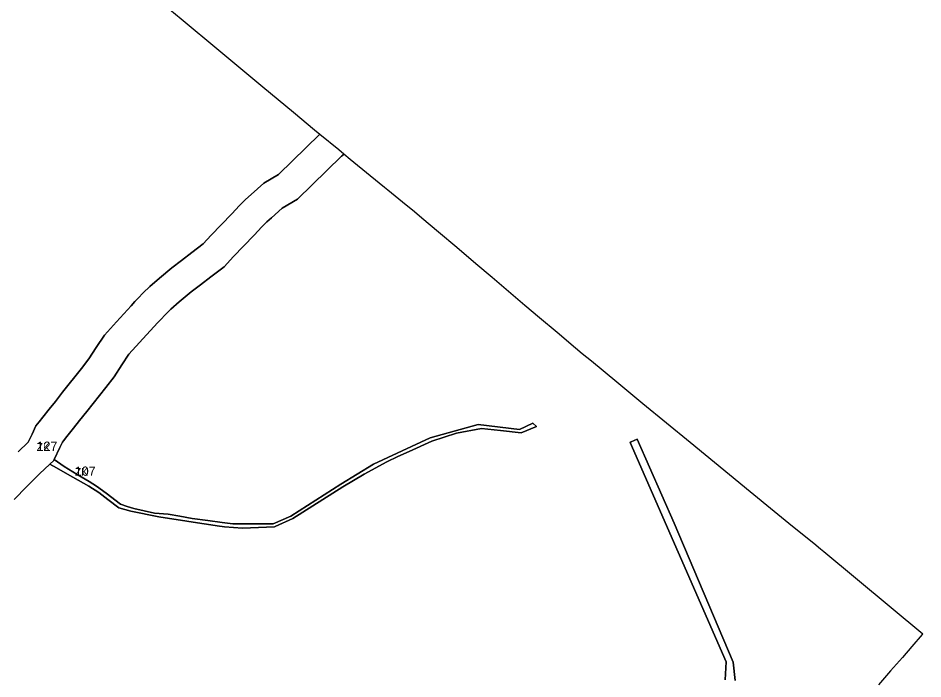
# Model space of a CAD drawing. Extents: x -537068 to -534056, y -1176840 to -1172401.
# Drawn here: x -534942 to -534355, y -1174646 to -1174218 of the extents above; entities that cross this region are included whole.
import ezdxf

# ---------------------------------------------------------------- set-up
doc = ezdxf.new("R2010")
doc.units = 0
for name, color, linetype in [('90640013', 7, 'Continuous'), ('90710023', 7, 'Continuous'), ('90750013', 7, 'Continuous'), ('ID_navrh', 7, 'Continuous')]:
    doc.layers.add(name, color=color, linetype=linetype)

msp = doc.modelspace()

# ---------------------------------------------------------------- linework, layer by layer
at = {"layer": '90640013'}
msp.add_lwpolyline([(-534483.43, -1174646.62), (-534482.82, -1174635.13), (-534544.96, -1174492.85), (-534544.28, -1174492.54), (-534540.56, -1174490.81), (-534516.48, -1174545.24), (-534478.25, -1174635.29), (-534477.06, -1174647.13)], dxfattribs=at)
at = {"layer": '90710023'}
msp.add_lwpolyline([(-534941.55, -1174498.93), (-534934.92, -1174492.67), (-534932.5, -1174487.55), (-534929.97, -1174482.19), (-534927.84, -1174479.51), (-534925.57, -1174476.65), (-534921.36, -1174471.33), (-534917.36, -1174466.29), (-534912.72, -1174460.43), (-534900.49, -1174444.99), (-534895.64, -1174438.72), (-534890.91, -1174431.52), (-534885.55, -1174423.46), (-534877.76, -1174414.85), (-534873.08, -1174409.69), (-534868.28, -1174404.39), (-534865.86, -1174401.72), (-534863.7, -1174399.5), (-534860.41, -1174396.1), (-534856.3, -1174391.86), (-534850, -1174386.58), (-534841.97, -1174379.85), (-534835.63, -1174374.98), (-534828.91, -1174369.82), (-534821.55, -1174364.16), (-534816.37, -1174358.72), (-534809.91, -1174351.94), (-534803.15, -1174344.84), (-534798.02, -1174339.45), (-534794.25, -1174335.5), (-534790.64, -1174332.32), (-534782.33, -1174324.99), (-534772.78, -1174319.35), (-534746, -1174293.24), (-534733.78, -1174303.25), (-534730.46, -1174305.96), (-534731.42, -1174306.96), (-534732.04, -1174307.56), (-534760.54, -1174335.35), (-534770.52, -1174341.25), (-534777.41, -1174347.32), (-534780.38, -1174349.94), (-534783.54, -1174353.25), (-534788.66, -1174358.63), (-534795.43, -1174365.73), (-534801.89, -1174372.51), (-534808.13, -1174379.07), (-534816.72, -1174385.68), (-534823.45, -1174390.84), (-534829.45, -1174395.45), (-534837.15, -1174401.91), (-534842.66, -1174406.52), (-534846.04, -1174410.01), (-534849.35, -1174413.43), (-534851.28, -1174415.41), (-534853.46, -1174417.82), (-534858.26, -1174423.12), (-534862.94, -1174428.28), (-534869.72, -1174435.77), (-534874.23, -1174442.55), (-534879.35, -1174450.35), (-534884.74, -1174457.32), (-534897.04, -1174472.85), (-534901.69, -1174478.71), (-534905.69, -1174483.75), (-534909.9, -1174489.07), (-534912.18, -1174491.95), (-534912.87, -1174492.82), (-534914.42, -1174496.09), (-534918.11, -1174503.91), (-534918.45, -1174504.62), (-534920.96, -1174506.99), (-534927.58, -1174513.24), (-534935.81, -1174521.55), (-534944.09, -1174529.91)], dxfattribs=at)
msp.add_lwpolyline([(-534920.96, -1174506.99), (-534918.45, -1174504.62), (-534918.11, -1174503.91), (-534911.75, -1174508.48), (-534903.27, -1174513.61), (-534895.53, -1174518.3), (-534890.67, -1174521.25), (-534884.57, -1174525.85), (-534875.3, -1174532.85), (-534870.88, -1174534.39), (-534866.59, -1174535.76), (-534859.86, -1174537.23), (-534853.19, -1174538.69), (-534844.4, -1174539.4), (-534836.83, -1174540.72), (-534828.78, -1174542.12), (-534818.52, -1174543.48), (-534809.35, -1174544.69), (-534802.36, -1174545.61), (-534776.33, -1174545.67), (-534764.95, -1174540.64), (-534732.52, -1174520.03), (-534711.23, -1174506.95), (-534686.74, -1174495.63), (-534674.53, -1174489.99), (-534643.44, -1174481.22), (-534616.63, -1174484.53), (-534608.11, -1174480.54), (-534605.76, -1174482.69), (-534615.7, -1174486.77), (-534629.08, -1174485.21), (-534641.32, -1174483.78), (-534657.61, -1174486.93), (-534673.45, -1174491.99), (-534688.29, -1174498.79), (-534695.46, -1174502.07), (-534702.74, -1174505.41), (-534717.31, -1174513.4), (-534731.12, -1174521.65), (-534744.09, -1174529.89), (-534763.58, -1174542.26), (-534774.98, -1174547.3), (-534775.48, -1174547.52), (-534796.2, -1174548.49), (-534807.85, -1174547.56), (-534812.51, -1174546.88), (-534816.77, -1174546.26), (-534825.24, -1174545.03), (-534832.16, -1174544.02), (-534850.47, -1174541.19), (-534868.48, -1174537.39), (-534876.27, -1174535.32), (-534883.41, -1174529.86), (-534889.21, -1174525.43), (-534895.69, -1174521.31), (-534902.53, -1174517.43), (-534909.64, -1174513.4), (-534916.77, -1174509.36)], close=True, dxfattribs=at)
at = {"layer": '90750013'}
for points in [[(-534850.54, -1174206.42), (-534835.97, -1174218.53), (-534811.5, -1174238.86), (-534801.22, -1174247.4), (-534782.96, -1174262.58), (-534763.17, -1174279.02), (-534749.56, -1174290.33), (-534746, -1174293.24), (-534772.78, -1174319.35), (-534782.33, -1174324.99), (-534790.64, -1174332.32), (-534794.25, -1174335.5), (-534798.02, -1174339.45), (-534803.15, -1174344.84), (-534809.91, -1174351.94), (-534816.37, -1174358.72), (-534821.55, -1174364.16), (-534828.91, -1174369.82), (-534835.63, -1174374.98), (-534841.97, -1174379.85), (-534850, -1174386.58), (-534856.3, -1174391.86), (-534860.41, -1174396.1), (-534863.7, -1174399.5), (-534865.86, -1174401.72), (-534868.28, -1174404.39), (-534873.08, -1174409.69), (-534877.76, -1174414.85), (-534885.55, -1174423.46), (-534890.91, -1174431.52), (-534895.64, -1174438.72), (-534900.49, -1174444.99), (-534912.72, -1174460.43), (-534917.36, -1174466.29), (-534921.36, -1174471.33), (-534925.57, -1174476.65), (-534927.84, -1174479.51), (-534929.97, -1174482.19), (-534932.5, -1174487.55), (-534934.92, -1174492.67), (-534941.55, -1174498.93)], [(-534944.09, -1174529.91), (-534935.81, -1174521.55), (-534927.58, -1174513.24), (-534920.96, -1174506.99), (-534916.77, -1174509.36), (-534909.64, -1174513.4), (-534902.53, -1174517.43), (-534895.69, -1174521.31), (-534889.21, -1174525.43), (-534883.41, -1174529.86), (-534876.27, -1174535.32), (-534868.48, -1174537.39), (-534850.47, -1174541.19), (-534832.16, -1174544.02), (-534825.24, -1174545.03), (-534816.77, -1174546.26), (-534812.51, -1174546.88), (-534807.85, -1174547.56), (-534796.2, -1174548.49), (-534775.48, -1174547.52), (-534774.98, -1174547.3), (-534763.58, -1174542.26), (-534744.09, -1174529.89), (-534731.12, -1174521.65), (-534717.31, -1174513.4), (-534702.74, -1174505.41), (-534695.46, -1174502.07), (-534688.29, -1174498.79), (-534673.45, -1174491.99), (-534657.61, -1174486.93), (-534641.32, -1174483.78), (-534629.08, -1174485.21), (-534615.7, -1174486.77), (-534605.76, -1174482.69), (-534608.11, -1174480.54), (-534616.63, -1174484.53), (-534643.44, -1174481.22), (-534674.53, -1174489.99), (-534686.74, -1174495.63), (-534711.23, -1174506.95), (-534732.52, -1174520.03), (-534764.95, -1174540.64), (-534776.33, -1174545.67), (-534802.36, -1174545.61), (-534809.35, -1174544.69), (-534818.52, -1174543.48), (-534828.78, -1174542.12), (-534836.83, -1174540.72), (-534844.4, -1174539.4), (-534853.19, -1174538.69), (-534859.86, -1174537.23), (-534866.59, -1174535.76), (-534870.88, -1174534.39), (-534875.3, -1174532.85), (-534884.57, -1174525.85), (-534890.67, -1174521.25), (-534895.53, -1174518.3), (-534903.27, -1174513.61), (-534911.75, -1174508.48), (-534918.11, -1174503.91), (-534914.42, -1174496.09), (-534912.87, -1174492.82), (-534912.18, -1174491.95), (-534909.9, -1174489.07), (-534905.69, -1174483.75), (-534901.69, -1174478.71), (-534897.04, -1174472.85), (-534884.74, -1174457.32), (-534879.35, -1174450.35), (-534874.23, -1174442.55), (-534869.72, -1174435.77), (-534862.94, -1174428.28), (-534858.26, -1174423.12), (-534853.46, -1174417.82), (-534851.28, -1174415.41), (-534849.35, -1174413.43), (-534846.04, -1174410.01), (-534842.66, -1174406.52), (-534837.15, -1174401.91), (-534829.45, -1174395.45), (-534823.45, -1174390.84), (-534816.72, -1174385.68), (-534808.13, -1174379.07), (-534801.89, -1174372.51), (-534795.43, -1174365.73), (-534788.66, -1174358.63), (-534783.54, -1174353.25), (-534780.38, -1174349.94), (-534777.41, -1174347.32), (-534770.52, -1174341.25), (-534760.54, -1174335.35), (-534732.04, -1174307.56), (-534731.42, -1174306.96), (-534730.46, -1174305.96), (-534726.33, -1174309.34), (-534713.39, -1174319.94), (-534704.17, -1174327.49), (-534701.93, -1174329.33), (-534692.44, -1174337.1), (-534684.83, -1174343.33), (-534680.04, -1174347.38), (-534669.22, -1174356.52), (-534657.42, -1174366.5), (-534645, -1174377), (-534634.4, -1174385.96), (-534623.75, -1174394.96), (-534613.17, -1174403.91), (-534603.71, -1174411.9), (-534592.27, -1174421.58), (-534580.43, -1174431.59), (-534576.11, -1174435.24), (-534570.13, -1174440.15), (-534553.67, -1174453.68), (-534536.75, -1174467.59), (-534521.39, -1174480.21), (-534506.13, -1174492.75), (-534480.58, -1174513.75), (-534467.19, -1174524.75), (-534464.98, -1174526.57), (-534454.04, -1174535.48), (-534439.81, -1174547.07), (-534426.11, -1174558.23), (-534421.64, -1174561.87), (-534419.61, -1174563.52), (-534355.38, -1174616.95), (-534355.78, -1174617.4), (-534362.47, -1174625.07), (-534368.7, -1174632.2), (-534376.27, -1174640.88), (-534380.19, -1174645.37), (-534384.14, -1174649.9)], [(-534477.06, -1174647.13), (-534478.25, -1174635.29), (-534516.48, -1174545.24), (-534540.56, -1174490.81), (-534544.28, -1174492.54), (-534544.96, -1174492.85), (-534482.82, -1174635.13), (-534483.43, -1174646.62)]]:
    msp.add_lwpolyline(points, dxfattribs=at)

# ---------------------------------------------------------------- texts
at = {"layer": '90710023'}
for p in [(-534929.49, -1174498.37), (-534904.72, -1174514.51)]:
    msp.add_text('ZK', height=5, rotation=360, dxfattribs=at).set_placement(p)
at = {"layer": 'ID_navrh'}
for s, p in [('127', (-534929.49, -1174498.37)), ('107', (-534904.72, -1174514.51))]:
    msp.add_text(s, height=6, rotation=360, dxfattribs=at).set_placement(p)

doc.saveas('drawing.dxf')
